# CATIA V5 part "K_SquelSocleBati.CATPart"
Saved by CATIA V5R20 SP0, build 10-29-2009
Part number: Squelette_socle_bati
Publications: "Plan_socle_bati", "Axe_pivot_socle_bati"
Bounding box of the stored display mesh (mm): x -171 to -131, y -142.303 to -142.303, z 0 to 0
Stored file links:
  G:\Khaled_CFAO_2011\ST2M\ST2M_GR2\jcoetard\Khaled\CAD_CATIA\K_SquelSocleBati.CATPart
  G:\Khaled_CFAO_2011\ST2M\ST2M_GR2\jcoetard\jcoetard\Maquette_jcoetard\Squelette_ecrou.CATPart
  G:\Khaled_CFAO_2011\ST2M\ST2M_GR2\jcoetard\jcoetard\Maquette_jcoetard\Squelette_tige.CATPart
  G:\Khaled_CFAO_2011\ST2M\ST2M_GR2\jcoetard\Khaled\CAD_CATIA\K_Squelette.CATProduct
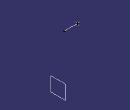
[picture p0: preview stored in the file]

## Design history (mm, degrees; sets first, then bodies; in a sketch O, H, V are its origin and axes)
Set1
  Point1 "Point_centre_écrou": linked copy from another document
Set2 "Set géométrique"
  Plane1 "Plan_socle_bati": type Offset, RefPlane yz-plane, Offset 30
  Line1 "Axe_pivot_socle_bati": type Normal, RefPoint Point1, RefSkin Plane1, Start 0, End 40
Body1 (main body)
